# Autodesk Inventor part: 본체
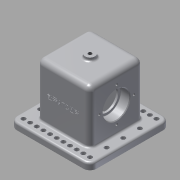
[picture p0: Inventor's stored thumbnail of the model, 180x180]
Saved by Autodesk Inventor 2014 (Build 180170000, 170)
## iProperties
Created: 2018-11
Part Number: 본체
Material: 알루미늄 6061
Document SubType Name: Modeling
Designer: kh
Mass: 1022.62 g
Surface Area: 782.359 cm^2
Volume: 377.352 cm^3
Density: 2.71 g/cm^3
Appearance: 알루미늄 - 평지
Author: kh
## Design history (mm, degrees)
sketch "스케치1"
  geometry: L1 (-60, -60)-(60, -60); L2 (60, -60)-(60, 60); L3 (60, 60)-(-60, 60); L4 (-60, 60)-(-60, -60); L5 (-60, -60)-(60, 60); L6 (60, -60)-(-60, 60); 1 further point
  constraints: 12 end point, 2 midpoint, 2 parallel, 1 horizontal, 1 perpendicular
  dimensions: "d0" = 120 distance of L3.end L2.end; "d1" = 120 distance of L2.end L1.end
extrude "돌출1" new body sketch "스케치1" distance "d2" = 10; taper "d3" = 0 deg
sketch "스케치2"
  geometry: L1 (40, -40)-(-40, -40); L2 (-40, -40)-(-40, 40); L3 (-40, 40)-(40, 40); L4 (40, 40)-(40, -40); L5 (40, -40)-(-40, 40); L6 (-40, -40)-(40, 40); 1 further point
  constraints: 12 end point, 2 midpoint, 2 parallel, 1 horizontal, 1 perpendicular
  dimensions: "d4" = 80 distance of L2.end L3.end; "d5" = 80 distance of L1.end L2.end
extrude "돌출2" join sketch "스케치2" distance "d6" = 90; taper "d7" = 0 deg
sketch "스케치3"
  geometry: C1 r 7.5 at (0, 0); 1 further point
  constraints: 1 centre point, 1 coincident
  dimensions: "d8" = 15 diameter of C1
extrude "돌출3" join sketch "스케치3" distance "d9" = 5; taper "d10" = 0 deg
sketch "스케치4"
  geometry: L1 (23, 30)-(-23, 30); L2 (-23, 30)-(-23, -30); L3 (-23, -30)-(23, -30); L4 (23, -30)-(23, 30); L5 (23, 30)-(-23, -30); L6 (-23, 30)-(23, -30); 1 further point
  constraints: 12 end point, 2 midpoint, 2 parallel, 1 horizontal, 1 perpendicular
  dimensions: "d11" = 46 distance of L2.end L3.end; "d12" = 60 distance of L1.end L2.end
extrude "돌출4" cut sketch "스케치4" distance "d13" = 80; taper "d14" = 0 deg
sketch "스케치5"
  geometry: L1 (-10, 100)-(-10, -20) reference; L2 (-10, 40)-(114.285, 40); C1 r 20 at (38, 40)
  constraints: 2 end point, 1 centre point, 1 perpendicular, 1 point on line
  dimensions: "d15" = 40 diameter of C1; "d16" = 48 distance from line of L1 C1.centre
extrude "돌출5" cut sketch "스케치5" distance "d17" = 14; taper "d18" = 0 deg
sketch "스케치6" dims "d19" = 52
  geometry: L1 (38, 40)-(64, 40); C1 r 20 at (38, 40) reference; 2 further points
  constraints: 2 end point, 1 coincident, 1 horizontal, 1 horizontal alignment, 3 other
hole "구멍1" sketch "스케치6" at (64, 40) diameter "d20" = 3.459; stored, may be unused: countersink angle "d24" = 90 deg, drill point angle "d26" = 118 deg; dims "d21" = 8, "d22" = 4, "d23" = 2, "d25" = 10
sketch "스케치7"
  geometry: C1 r 16.5 at (0, 0); C2 r 20 at (0, 0) reference; 1 further point
  constraints: 1 centre point, 1 concentric
  dimensions: "d30" = 33 diameter of C1
extrude "돌출6" cut sketch "스케치7" stored distance "d31" = 14; taper "d32" = 0 deg
hole "구멍2" diameter "d35" = 5.459; stored, may be unused: countersink angle "d39" = 90 deg, drill point angle "d41" = 0 deg; dims "d33" = 10, "d34" = 10, "d36" = 8, "d37" = 4, "d38" = 2, "d40" = 10
sketch "스케치8"
  geometry: 2 further points
  dimensions: "d42" = 50 horizontal distance of point (-50, 50) point (0, 0); "d43" = 50 horizontal distance of point (0, 0) point (-50, 50)
hole "구멍3" sketch "스케치8" at (-50, 50) diameter "d44" = 6.6; stored, may be unused: countersink angle "d48" = 90 deg, drill point angle "d50" = 0 deg; dims "d45" = 8, "d46" = 4, "d47" = 2, "d49" = 10
fillet "모깎기1" dims "d57" = 10, "d58" = 8, "d59" = 3
fillet "모깎기2" dims "d60" = 3
fillet "모깎기3" dims "d61" = 8
chamfer "모따기1" distance "d62" = 1; stored, may be unused: second distance "d63" = 2, angle "d64" = 45 deg
fillet "모깎기4" dims "d65" = 0.6
fillet "모깎기5" dims "d66" = 3
fillet "모깎기6" dims "d67" = 3
node "작업 평면1"
sketch "스케치9"
  geometry: L1 (8.136, 38.377)-(55.864, 38.377); L2 (55.864, 38.377)-(55.864, 31.623); L3 (55.864, 31.623)-(8.136, 31.623); L4 (8.136, 31.623)-(8.136, 38.377); L5 (8.136, 35)-(55.864, 35); L6 (32, 38.377)-(32, 31.623); L7 (32, -13)-(32, 76.221); L8 (-18, -13)-(82, -13) reference
  constraints: 6 end point, 4 midpoint, 2 collinear, 1 vertical, 2 other
  dimensions: "d69" = 48 distance between parallel lines of L8 L5
feature "엠보싱1" sketch "스케치9" dims "d0" = 120, "d1" = 120, "d70" = 0.5, "d71" = 0
fillet "모깎기7" dims "d72" = 3
node "솔리드1"
pattern_circular "원형 패턴1" dims angle "d28" = 360 deg
mirror "대칭1"
pattern_linear "직사각형 패턴1" dims "d53" = 10
pattern_linear "직사각형 패턴2" dims "d56" = 25
mirror "대칭2"
mirror "대칭3"
other parameters: "d68" = 34
